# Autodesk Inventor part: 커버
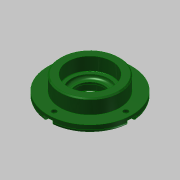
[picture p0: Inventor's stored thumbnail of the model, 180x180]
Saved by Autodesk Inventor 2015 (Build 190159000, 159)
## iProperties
Company: 한국ATC센터
Created: 2016-04
Part Number: 커버
Document SubType Name: Modeling
Designer: mdu
Density: 7.86 g/cm^3
Mass: 351.567 g
Surface Area: 161.165 cm^2
Volume: 44.7286 cm^3
Material: 강철, 연강
Appearance: 진녹색
Author: mdu
Revision Number: 1
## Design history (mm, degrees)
sketch "스케치1"
  geometry: C1 r 38 at (0, 0); 1 further point
  constraints: 1 centre point, 1 coincident
  dimensions: "d0" = 76 diameter of C1
extrude "돌출1" new body sketch "스케치1" distance "d1" = 7; taper "d2" = 0 deg
sketch "스케치2"
  geometry: C1 r 27 at (0, 0); 1 further point
  constraints: 1 centre point, 1 coincident
  dimensions: "d3" = 54 diameter of C1
extrude "돌출2" join sketch "스케치2" distance "d4" = 13; taper "d5" = 0 deg
sketch "스케치3"
  geometry: C1 r 20 at (0, 0); 1 further point
  constraints: 1 centre point, 1 coincident
  dimensions: "d6" = 40 diameter of C1
extrude "돌출3" join sketch "스케치3" distance "d7" = 5; taper "d8" = 0 deg
hole "구멍1" diameter "d11" = 25; stored, may be unused: countersink angle "d15" = 90 deg, drill point angle "d17" = 118 deg; dims "d9" = 10, "d10" = 10, "d12" = 6, "d13" = 32, "d14" = 8.3, "d16" = 8
hole "구멍2" diameter "d20" = 34; stored, may be unused: countersink angle "d24" = 90 deg, drill point angle "d26" = 0 deg; dims "d18" = 10, "d19" = 10, "d21" = 6, "d22" = 40, "d23" = 12, "d25" = 3
fillet "모깎기2" dims "d34" = 3
fillet "모깎기1" dims "d27" = 0.3
chamfer "모따기1" distance "d28" = 1; stored, may be unused: second distance "d29" = 2, angle "d30" = 45 deg
chamfer "모따기2" distance "d31" = 0.8; stored, may be unused: second distance "d32" = 2, angle "d33" = 30 deg
sketch "스케치4" dims "d35" = 65
  geometry: 3 further points
  constraints: 2 horizontal alignment, 1 coincident, 2 other
hole "구멍3" sketch "스케치4" at (32.5, 0) diameter "d36" = 4.5; stored, may be unused: countersink angle "d40" = 90 deg, drill point angle "d42" = 118 deg; dims "d37" = 6, "d38" = 8, "d39" = 4.4, "d41" = 13
sketch "스케치5"
  geometry: L1 (0, 4)-(5.5, 4); L2 (5.5, 4)-(5.5, -4); L3 (5.5, -4)-(0, -4); L4 (0, -4)-(0, 4); C1 r 2.25 at (0, 0) reference; C2 r 38 at (-32.5, 0) reference; 2 further points
  constraints: 8 end point, 3 horizontal, 2 parallel, 1 perpendicular, 1 tangent, 1 vertical alignment, 1 other
extrude "돌출4" cut sketch "스케치5" stored distance "d47" = 24.5; taper "d48" = 0 deg
node "솔리드1"
pattern_circular "원형 패턴1" dims angle "d44" = 360 deg
pattern_circular "원형 패턴2" dims angle "d50" = 360 deg
node "투영된 루프1"
